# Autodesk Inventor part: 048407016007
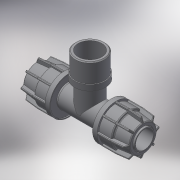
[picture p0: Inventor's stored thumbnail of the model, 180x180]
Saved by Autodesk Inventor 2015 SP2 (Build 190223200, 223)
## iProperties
Created: 2017-08
Part Number: 048407016007
Material: Generic
Description: PLASSON IRRIFIT TEE 16-3/4"-16
Document SubType Name: Modeling
Designer: KIM
Density: 1 g/cm^3
Appearance: Default
Author: KIM
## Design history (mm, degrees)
derived "048407.ipt"
feature "Solid1::048407.ipt"
tag "TaggingFeature1"
body "Solid1"
other parameters: "d5" = 29.7, "d6" = 14.04, "d10" = 34, "d22" = 20.8, "d24" = 4.05, "d25" = 30.6, "d26" = 27.2, "d31" = 0.8, "d49" = 1.7, "d50" = 0, "d58" = 0.48, "d61" = 360 deg, "d77" = 16, "d78" = 6 deg, "d80" = 17.6, "d81" = 49, "d82" = 2.16, "d84" = 5 deg, "d85" = 70 deg, "d86" = 32.3, "d87" = 0.81, "d88" = 0, "d100" = 19.76, "d101" = 1.62, "d102" = 0, "d103" = 26.441, "d104" = 27.76305, "d105" = 17, "d106" = 45, "d107" = 15.8646, "d108" = 21.1528, "d109" = 18.7, "d110" = 21.1528, "d111" = 22.1, "d113" = 0.79323, "d117" = 0, "d119" = 0, "d_" = 16, "E_" = 34, "H_" = 98, "l_" = 27, "A_" = 45, "l_2" = 17, "R_" = 26.441, "d99" = 20.8
